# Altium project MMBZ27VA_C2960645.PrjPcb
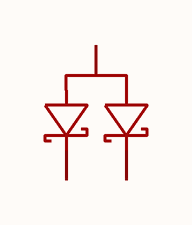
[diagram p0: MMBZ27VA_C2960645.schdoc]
1 sheet, 1 parts. Net scope: global (net labels, ports and power ports of the same name join across sheets).

## Sheet MMBZ27VA_C2960645.schdoc
size 127 x 101 mm

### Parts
U?  mmbz27va_c2960645  [SOT-23-3_L2.9-W1.3-P1.90-LS2.4-BR]  (value not drawn)

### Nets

Not connected (* = marked no-connect by the designer): U? 1 2 3

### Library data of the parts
U? = mmbz27va_c2960645: 极性:单向;反向截止电压(Vrwm):22V;钳位电压:40V;峰值脉冲电流(Ipp):1A;峰值脉冲功率(Ppp):24W;击穿电压(VBR):25.65V;; Manufacturer: JSMSEMI(杰盛微); AddInBom: yes; ModelId: c62791f0466c4ae2a892c056b845b0ca; ModelName: SOT-23-3P_L2.9-W1.3-H1.0-LS2.4-P0.95; ModelTransform: 98.425,114.173,0,180,0,0,0.0005,-0.0005,0; Polarity: 单向; Reverse Stand-Off Voltage (Vrwm): 22V; Clamping Voltage: 40V; Peak Pulse Current (Ipp): 1A; Peak Pulse Power Dissipation (Ppp): 24W; Voltage - Breakdown: 25.65V; Reverse Leakage Current (Ir): 50uA; Number of Channels: 双路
